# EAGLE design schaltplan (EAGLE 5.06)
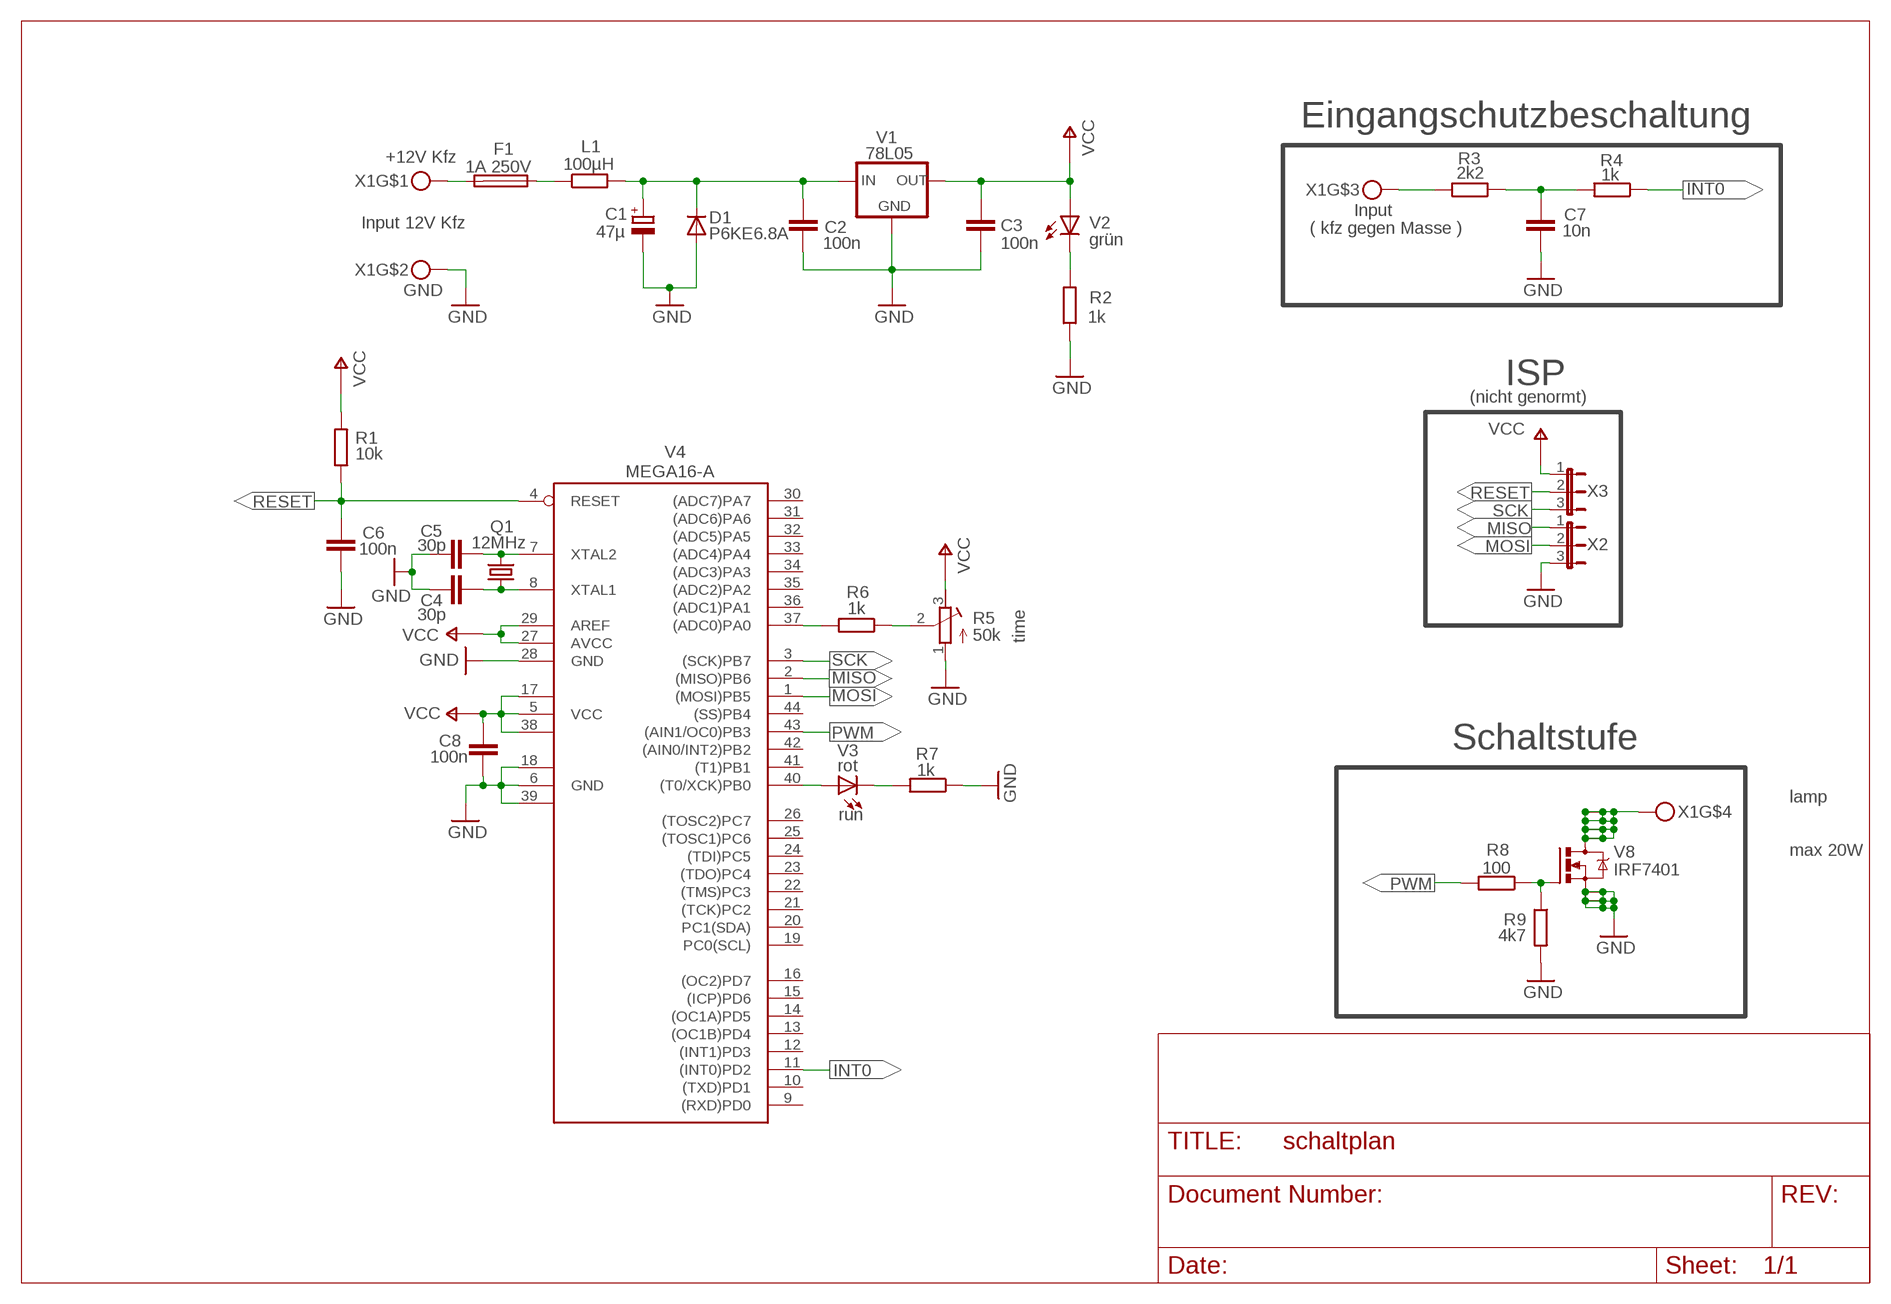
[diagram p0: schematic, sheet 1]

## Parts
C1  47µ  CE_2,5-5  [2,5-5]
C2  100n  C-EUC1206  [C1206]
C3  100n  C-EUC1206  [C1206]
C4  30p  C-EUC0805  [C0805]
C5  30p  C-EUC0805  [C0805]
C6  100n  C-EUC1206  [C1206]
C7  10n  C-EUC1206  [C1206]
C8  100n  C-EUC1206  [C1206]
D1  P6KE6.8A  1N4004  [DO41-10]
F1  1A 250V  TE5  [TE5]
L1  100µH  R-EU_0207/10  [0207/10]
Q1  12MHz  CRYSTALHC49UP  [HC49UP]
R1  10k  R-EU_M1206  [M1206]
R2  1k  R-EU_M1206  [M1206]
R3  2k2  R-EU_M1206  [M1206]
R4  1k  R-EU_M1206  [M1206]
R5  50k  R-TRIMM3165W  [RTRIM3165W]
R6  1k  R-EU_M1206  [M1206]
R7  1k  R-EU_M1206  [M1206]
R8  100  R-EU_M1206  [M1206]
R9  4k7  R-EU_M1206  [M1206]
V1  78L05  78LXX  [78LXX]
V2  grün  LEDCHIPLED_1206  [CHIPLED_1206]
V3  rot  LEDCHIPLED_1206  [CHIPLED_1206]
V4  MEGA16-A  [TQFP44]
V8  IRF7401  N-MOSFET-SO8S  [SO-08]
X1  MKDS3/4_5,08  [MKDS3/4_5,08]
X2  JMP3  [JMP3]
X3  JMP3  [JMP3]

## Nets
GND: C1.- C2.2 C3.2 C4.1 C5.1 C6.2 C7.2 C8.2 D1.A R2.1 R5.1(E) R7.1 R9.2 V1.GND V4.6(GND) V4.18(GND1) V4.28(GND) V4.39(GND2) V8.1(S) V8.2(S) V8.3(S) X1.P$2 X2.3
INT0: R4.1 V4.11((INT0)PD2)
MISO: V4.2((MISO)PB6) X2.1
MOSI: V4.1((MOSI)PB5) X2.2
N$1: F1.2 X1.P$1
N$2: F1.1 L1.1
N$3: C1.+ C2.1 D1.C L1.2 V1.IN
N$4: R3.2 X1.P$3
N$5: C7.1 R3.1 R4.2
N$6: C5.2 Q1.2 V4.7(XTAL2)
N$7: R2.2 V2.C
N$8: C4.2 Q1.1 V4.8(XTAL1)
N$9: R6.2 V4.37((ADC0)PA0)
N$10: R5.2(S) R6.1
N$11: R7.2 V3.C
N$12: R8.1 R9.1 V8.4(G)
N$13: V8.5(D) V8.6(D) V8.7(D) V8.8(D) X1.P$4
N$14: V3.A V4.40((T0/XCK)PB0)
PWM: R8.2 V4.43((AIN1/OC0)PB3)
RESET: C6.1 R1.1 V4.4(RESET) X3.2
SCK: V4.3((SCK)PB7) X3.3
VCC: C3.1 C8.1 R1.2 R5.3(A) V1.OUT V2.A V4.5(VCC) V4.17(VCC1) V4.27(AVCC) V4.29(AREF) V4.38(VCC2) X3.1
Unconnected: V4.9((RXD)PD0) V4.10((TXD)PD1) V4.12((INT1)PD3) V4.13((OC1B)PD4) V4.14((OC1A)PD5) V4.15((ICP)PD6) V4.16((OC2)PD7) V4.19(PC0(SCL)) V4.20(PC1(SDA)) V4.21((TCK)PC2) V4.22((TMS)PC3) V4.23((TDO)PC4) V4.24((TDI)PC5) V4.25((TOSC1)PC6) V4.26((TOSC2)PC7) V4.30((ADC7)PA7) V4.31((ADC6)PA6) V4.32((ADC5)PA5) V4.33((ADC4)PA4) V4.34((ADC3)PA3) V4.35((ADC2)PA2) V4.36((ADC1)PA1) V4.41((T1)PB1) V4.42((AIN0/INT2)PB2) V4.44((SS)PB4)

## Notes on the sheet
- Eingangschutzbeschaltung
- +12V Kfz
- Input 12V Kfz | Input
- ( kfz gegen Masse )
- GND
- ISP
- (nicht genormt)
- time
- Schaltstufe
- lamp
- run
- max 20W

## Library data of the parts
C1 = user_analog:CE*: Elko
C2-C8 = rcl:C-EU: CAPACITOR, European symbol
D1 = diode:1N4004: DIODE
F1 = fuse:TE5: FUSE
L1 R1-R4 R6-R9 = rcl:R-EU_: RESISTOR, European symbol
Q1 = crystal:CRYSTAL: CRYSTAL
R5 = rcl:R-TRIMM: Trimm resistor
V1 = v-reg:78LXX: VOLTAGE REGULATOR
V2 V3 = led:LED: LED
V4 = atmel:MEGA16: MICROCONTROLLER 16 Kbytes FLASH 1 kbytes SRAM 512 bytes EEPROM USART 8-channel 10 bit ADC Source: avr.lbr
V8 = lib_auschaltverzögerung:N-MOSFET-SO8: N-Channel MOSFET Example: FDS7760A; N-Channel Logic Level PowerTrench® MOSFET FDS2572; N-Channel UltraFET® Trench MOSFET Source: www.fairchildsemi.com
X1 = lib_auschaltverzögerung:MKDS3/4_5,08: Leiterplattenklemme 4-polig
X2 X3 = user_elektro:JMP3: Jumper 3-polig

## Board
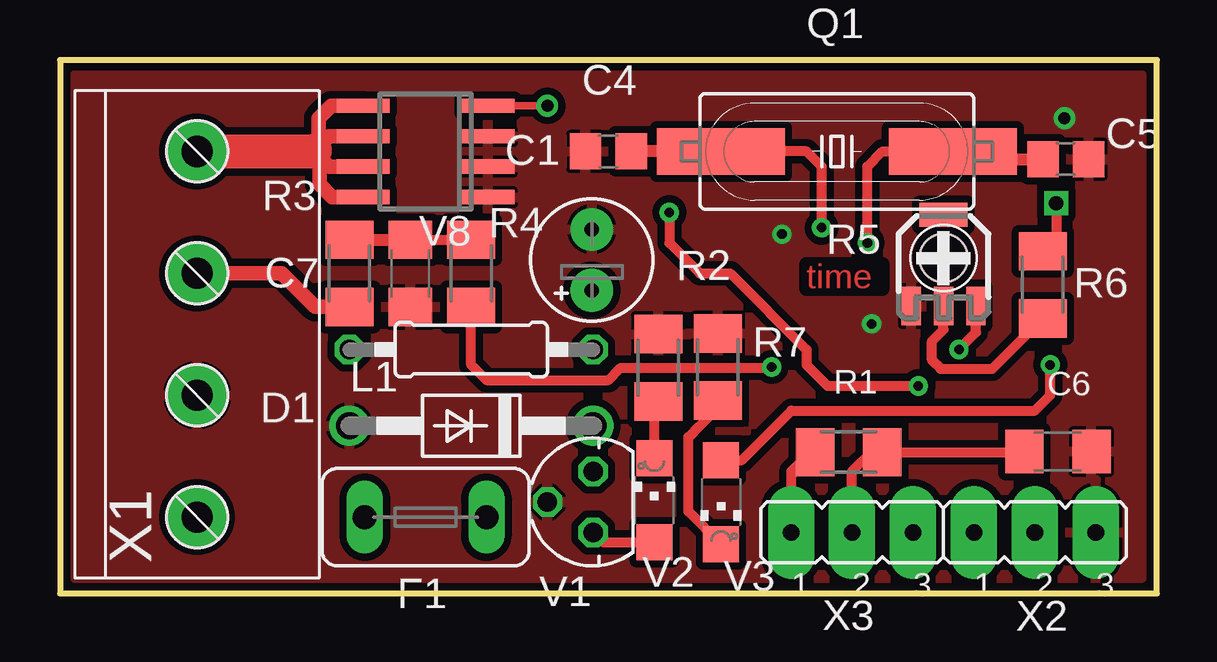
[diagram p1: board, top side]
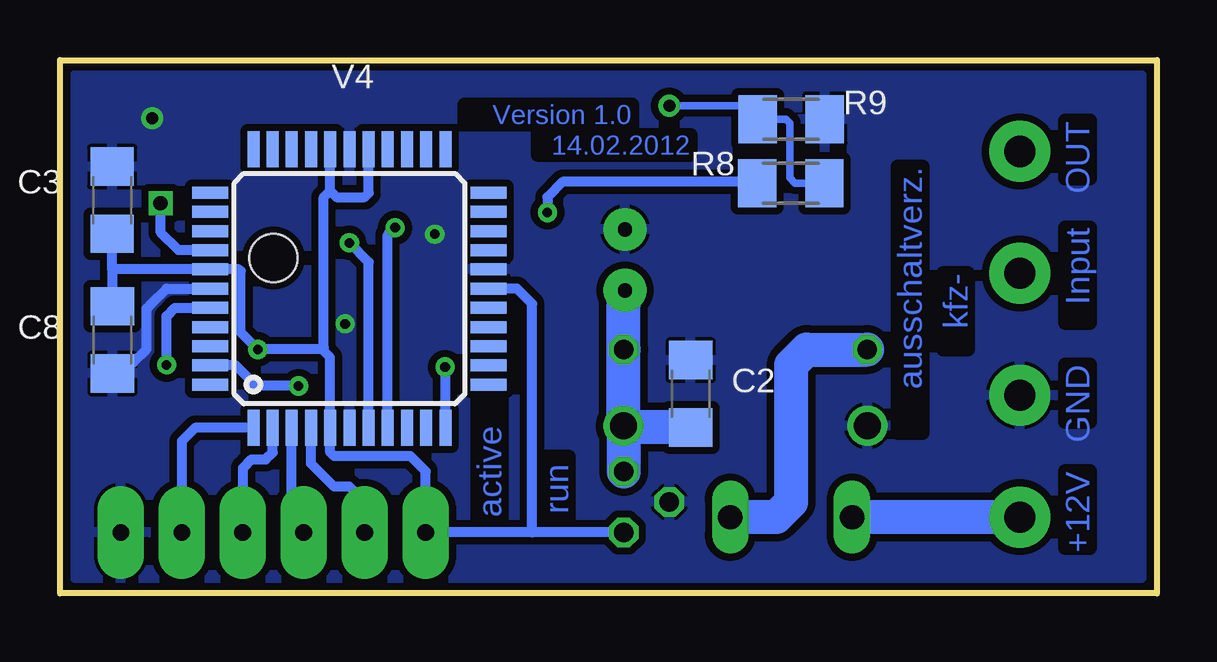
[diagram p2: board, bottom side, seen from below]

Size 45.72 x 22.23 mm. Coordinates in mm from the lower left corner, seen from the top.
Outline: 0,0 45.72,0 45.72,22.23 0,22.23 0,0
Copper layers (1*16): Top 0.035mm / dielectric 1.5mm / Bottom 0.035mm
Design rules "platinensammler_01": minimum track width 0.15mm, minimum drill 0.3mm, track to track 0.15mm, track to pad 0.15mm, pad to pad 0.15mm, via to via 0.15mm, smd to smd 0mil, copper to edge 0.15mm, drill to drill 0.2mm, minimum pad ring 0.2mm, minimum via ring 0.2mm, stop-mask expansion 4mil, vias tented up to drill 0.8mm, thermal gap 0.15mm

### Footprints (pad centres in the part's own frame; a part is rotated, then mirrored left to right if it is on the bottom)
2,5-5 = drill 0.6 pad 1.778 round: + -1.27,0; - 1.27,0
C1206 = smd 1.6 x 1.8: 1 -1.4,0; 2 1.4,0
C0805 = smd 1.3 x 1.5: 1 -0.95,0; 2 0.95,0
DO41-10 = drill 1.118 round: A 5.08,0; C -5.08,0
TE5 = drill 1.016 long: 1 -2.54,0; 2 2.54,0
0207/10 = drill 0.813 octagon: 1 -5.08,0; 2 5.08,0
HC49UP = smd 5.334 x 1.93: 1 -4.826,0; 2 4.826,0
M1206 = smd 1.6 x 2: 1 -1.4,0; 2 1.4,0
RTRIM3165W = smd 0.8 x 1.6: 1 -1.35,-2; 2 0,-2; 3 1.35,-2 | smd 2 x 1: 4 0,1.8 | hole 2: 0,0
78LXX = drill 0.813 octagon: GND 0,1.905; IN 1.27,0; OUT -1.27,0
CHIPLED_1206 = smd 1.5 x 1.5: A 0,-1.75; C 0,1.75
TQFP44 = smd 1.5 x 0.5: 1 -5.8,4; 2 -5.8,3.2; 3 -5.8,2.4; 4 -5.8,1.6; 5 -5.8,0.8; 6 -5.8,0; 7 -5.8,-0.8; 8 -5.8,-1.6; 9 -5.8,-2.4; 10 -5.8,-3.2; 11 -5.8,-4; 23 5.8,-4; 24 5.8,-3.2; 25 5.8,-2.4; 26 5.8,-1.6; 27 5.8,-0.8; 28 5.8,0; 29 5.8,0.8; 30 5.8,1.6; 31 5.8,2.4; 32 5.8,3.2; 33 5.8,4 | smd 0.5 x 1.5: 12 -4,-5.8; 13 -3.2,-5.8; 14 -2.4,-5.8; 15 -1.6,-5.8; 16 -0.8,-5.8; 17 0,-5.8; 18 0.8,-5.8; 19 1.6,-5.8; 20 2.4,-5.8; 21 3.2,-5.8; 22 4,-5.8; 34 4,5.8; 35 3.2,5.8; 36 2.4,5.8; 37 1.6,5.8; 38 0.8,5.8; 39 0,5.8; 40 -0.8,5.8; 41 -1.6,5.8; 42 -2.4,5.8; 43 -3.2,5.8; 44 -4,5.8
SO-08 = smd 0.6 x 2.2: 1 -1.905,-2.6; 2 -0.635,-2.6; 3 0.635,-2.6; 4 1.905,-2.6; 5 1.905,2.6; 6 0.635,2.6; 7 -0.635,2.6; 8 -1.905,2.6
MKDS3/4_5,08 = drill 1.3 pad 2.54 round: P$1 -7.62,0; P$2 -2.54,0; P$3 2.54,0; P$4 7.62,0
JMP3 = drill 0.7 pad 1.93 long: 1 -2.54,0; 2 0,0; 3 2.54,0

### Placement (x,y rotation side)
C1  22.17,13.9 90 top
C2  19.43,8.32 90 bottom
C3  43.54,16.38 90 bottom
C4  22.86,18.41 0 top
C5  41.93,18.1 180 top
C6  41.6,5.92 0 top
C7  14.61,13.34 270 top
C8  43.53,10.56 270 bottom
D1  17.14,6.99 180 top
F1  15.24,3.17 180 top
L1  17.14,10.16 0 top
Q1  32.38,18.41 0 top
R1  32.88,5.89 180 top
R2  24.94,9.4 270 top
R3  12.06,13.34 270 top
R4  17.14,13.34 90 top
R5  36.83,13.97 0 top
R6  40.96,12.86 90 top
R7  27.42,9.43 270 top
R8  15.25,17.09 180 bottom
R9  15.24,19.76 0 bottom
V1  22.23,3.81 90 top
V2  24.78,3.88 0 top
V3  27.55,3.81 180 top
V4  33.66,12.7 90 bottom
V8  15.24,18.41 90 top
X1  5.71,10.79 90 top
X2  40.64,2.54 0 top
X3  33.02,2.54 0 top

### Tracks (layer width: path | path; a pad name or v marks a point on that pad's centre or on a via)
GND  (via drill 0.4, 0.5)
  Bottom 0.406: V4.39 41.27,12.7 41.91,12.06 42.11,11.87 42.11,10.18 42.68,9.61 43.09,9.61
  Bottom 0.508: 43.09,9.61 C8.2
  other vias: 30.09,14.97 41.87,19.8 33.83,11.23
  pour Bottom (isolate 0.305): 45.09,21.59 0.64,21.59 0.64,0.64 45.09,0.64
  pour Top (isolate 0.305): 45.09,21.59 0.64,21.59 0.64,0.64 45.09,0.64
INT0  (via drill 0.4)
  Top 0.406: v29.67,9.43 29.64,9.4 23.37,9.4 22.86,8.89 17.78,8.89 17.14,9.53 R4.1
  Bottom 0.406: v29.67,9.43 29.67,6.91 V4.11
  Bottom 0.508: V4.11 29.67,6.91
MISO
  Bottom 0.406: V4.2 36.85,5.87 37.14,5.58 37.74,5.58 38.09,5.24 X2.1
MOSI
  Bottom 0.406: V4.1 40.09,6.9 40.64,6.35 X2.2
N$1
  Bottom 1.422: X1.P$1 F1.2
N$2
  Bottom 1.422: L1.1 14.61,10.16 15.24,9.53 15.24,3.81 15.88,3.17 F1.1
N$3
  Bottom 1.422: D1.C L1.2 22.23,12.06 C1.+ | D1.C V1.IN | C2.1 22.16,6.92 D1.C
N$4
  Top 0.61: R3.2 10.64,11.94 9.24,13.34 X1.P$3 | R3.2
N$5
  Top 0.406: C7.1 R4.2
  Top 0.508: R3.1 C7.1
N$6  (via drill 0.4)
  Top 0.406: v33.66,14.61 33.66,17.78 34.29,18.41 Q1.2
  Top 0.508: Q1.2 39.29,18.08 C5.2
  Bottom 0.406: V4.7 32.85,13.8 v33.66,14.61
N$7
  Top 0.406: V2.C 24.78,7.2 R2.2
N$8  (via drill 0.4)
  Top 0.406: v31.75,15.24 31.75,17.78 31.11,18.41 Q1.1
  Top 0.508: Q1.1 C4.2
  Bottom 0.406: V4.8 32.05,14.94 v31.75,15.24
N$9  (via drill 0.6)
  Top 0.406: v41.53,16.26 41.53,14.82 R6.2
  Bottom 0.406: V4.37 40.78,14.3 41.52,15.04 41.52,16.24 v41.53,16.26
N$10
  Top 0.406: R6.1 38.86,9.35 36.71,9.35 36.35,9.71 36.35,10.52 36.83,10.99 R5.2
N$11
  Top 0.406: R7.2 27.42,7.74 26.67,6.99 26.66,6.99 26.2,6.52 26.2,3.42 V3.C
N$12  (via drill 0.5)
  Top 0.305: v20.32,20.32 V8.4
  Bottom 0.305: R8.1 13.86,17.1 15.07,17.1 15.3,17.32 15.3,19.59 15.46,19.76 R9.1 17.2,20.32 v20.32,20.32
N$13
  Top 0.61: V8.8 11.35,16.51 10.82,17.04 10.82,18.19 | 10.59,18.41 10.82,18.19 | V8.5 11.29,20.32 10.78,19.8 10.78,18.6 | 10.63,18.46 10.78,18.6 | V8.6 11.22,19.05 10.78,18.6 | V8.7 11.22,17.78 10.82,18.19
  Top 1.422: 10.63,18.46 10.59,18.41 X1.P$4
N$14  (via drill 0.4)
  Top 0.406: V3.A 28.42,5.56 30.48,7.62 40.64,7.62 41.27,8.26 v41.27,9.53
  Bottom 0.406: v41.27,9.53 41.27,11.55 40.93,11.9 V4.40
  Bottom 0.508: V4.40
PWM  (via drill 0.4)
  Top 0.406: v25.4,15.88 25.4,14.61 26.67,13.34 27.94,13.34 31.11,10.16 31.11,9.53 32,8.64 v35.78,8.64
  Bottom 0.406: R8.2 16.71,17.14 24.77,17.14 25.4,16.51 v25.4,15.88 | V4.43 38.39,9.5 37.63,8.74 37.62,8.74 37.53,8.65 35.79,8.65 v35.78,8.64
RESET
  Top 0.406: C6.1 40.17,5.89 R1.1 33.83,5.89 33.02,5.08 X3.2
  Bottom 0.406: V4.4 35.26,5.41 34.29,4.45 33.66,4.45 33.02,3.81 X3.2
SCK
  Bottom 0.406: V4.3 36.05,3.04 X3.3
VCC  (via drill 0.4)
  Top 0.406: V2.A 22.63,2.13 V1.OUT | R1.2 31.29,5.89 30.48,5.08 X3.1 | R5.3 38.18,10.88 v37.47,10.17
  Bottom 0.406: V1.OUT 26.04,2.54 | 26.04,2.54 X3.1 30.48,5.08 31.11,5.71 34.29,5.71 34.45,5.88 V4.5 34.46,6.91 34.46,9.83 34.8,10.17 | V4.17 26.67,12.7 26.04,12.06 26.04,2.54 | V4.27 32.85,16.68 33.02,16.51 34.19,16.51 34.46,16.78 | 34.46,16.78 V4.29 | 34.46,16.78 34.73,16.51 34.73,10.24 34.8,10.17 | 43.55,13.52 43.52,13.5 V4.38 38.25,13.5 38.18,13.43 38.18,10.88 v37.47,10.17 34.8,10.17 | 43.55,13.52 C3.1 | 43.54,11.97 43.54,13.52 43.55,13.52
  Bottom 0.508: 43.54,11.97 C8.1

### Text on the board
Top: time
Bottom: OUT | Version 1.0 | 14.02.2012 | ausschaltverz. | Input | kfz- | GND | +12V | run | active
Infos: switched | time delay | Input | GND | +12V | +5V | SCK | MOSI | MISO | GND | Power | active | Reset | ISP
